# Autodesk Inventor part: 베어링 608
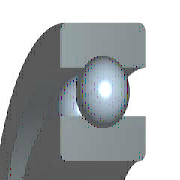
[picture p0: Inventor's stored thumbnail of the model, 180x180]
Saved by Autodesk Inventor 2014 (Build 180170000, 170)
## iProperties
IsCustomPart: 1
Created: 2012-02
Part Number: 베어링 608
Material: 강철, 연강
Description: 깊은 그루브 볼 베어링
Document SubType Name: Modeling
Standard: KS B 2023
Designer: mduedu
Standards Organization: KS
Language: ko-KR
Size Designation: 608 - 8 x 22 x 7
Categories: <MemberInstance><Categories><Category DisplayName="샤프트 부품" InternalName="7f7aeb1f-a693-4053-b835-cee3144e0d98" Mnemonic="SHFT"><Category DisplayName="베어링" Inter
Density: 7.86 g/cm^3
Appearance: 주황색
Mass: 10.9696 g
Surface Area: 20.0754 cm^2
Volume: 1.39562 cm^3
Author: mduedu
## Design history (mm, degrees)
sketch "스케치" dims "d0" = 3.64 (= -0.26 x WD + 0.26 x BD)
  geometry: L1 (1.68, 7.5)-(5.32, 7.5); L2 (3.5, 7.5)-(3.5, 5.68); L3 (3.5, 7.5)-(3.5, 9.32); L4 (2.148, 6.282)-(0, 6.282); L5 (0, 4)-(7, 4); L6 (2.148, 8.718)-(0, 8.718); L7 (0, 11)-(7, 11); L8 (7, 4)-(7, 6.282); L9 (4.852, 6.282)-(7, 6.282); L10 (4.852, 8.718)-(7, 8.718); L11 (7, 11)-(7, 8.718); L12 (-1.4, 0)-(8.4, 0) reference; L13 (0, -0.3)-(0, 5.3) reference
  constraints: 22 end point, 4 point on line, 2 collinear, 2 perpendicular, 2 symmetric about line, 1 midpoint, 1 parallel, 14 other
  dimensions: "d9" = 8 diameter of L5 L12 (= WD); "d11" = 22 diameter of L7 L12 (= BD); "d12" = 7 distance between parallel lines of L8 L13 (= KB); "d13" = 12.564 diameter of L9 L12 (= 0.326 x BD + 0.674 x WD)
revolve "본체" stored, may be unused: angle "d6" = 90 deg
revolve "볼" stored, may be unused: angle "d7" = 90 deg
pattern_circular "IDS_ARRAYBALL[SIMPL:T]" dims angle "d3" = 360 deg
body "Solid1"
fillet "모깎기1" dims "d1" = 0.3 (= KRS)
other parameters: "WD" = 8 [user parameter; used in 5 equation terms], "BD" = 22 [user parameter; used in 5 equation terms], "KB" = 7 [user parameter; used in 1 equation term], "KRS" = 0.3 [user parameter; used in 1 equation term], "d4" = 0, "d5" = 0, "d8" = 0, "d14" = 0, "d15" = 0, "BBA" = 0 [user parameter], "BC0" = 1370000 [user parameter], "BC" = 3250000 [user parameter], "BR" = 11 (= 0.5 x BD) [user parameter], "WR" = 4 (= 0.5 x WD) [user parameter]
